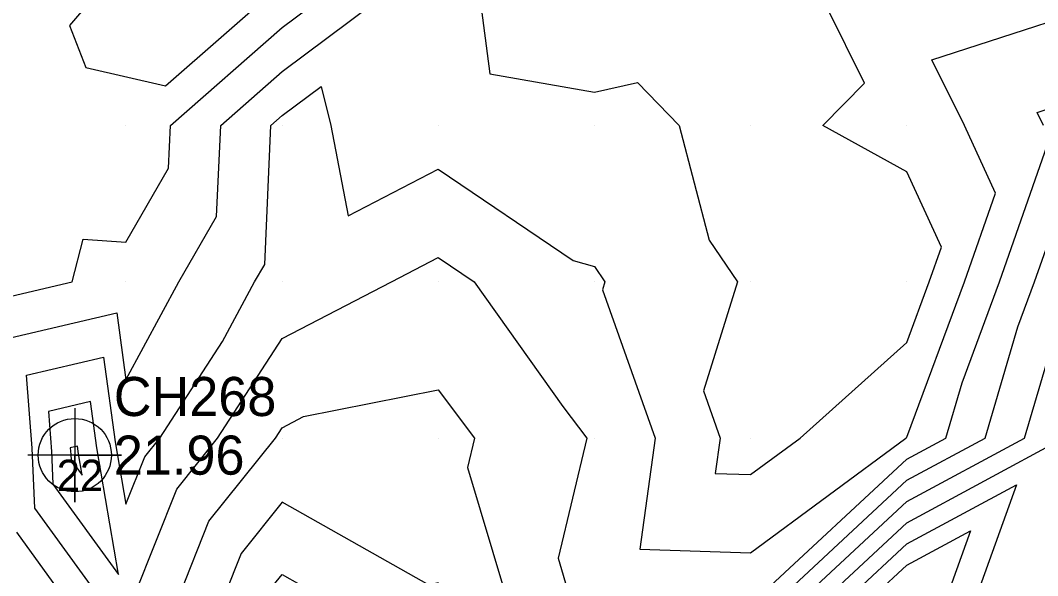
# Model space of a CAD drawing. Extents: x 2531902 to 2533249, y 715219 to 716099.
# Drawn here: x 2533033.2 to 2533098.4, y 715851.2 to 715886.7 of the extents above; entities that cross this region are included whole.
import ezdxf

# ---------------------------------------------------------------- set-up
doc = ezdxf.new("R2010")
doc.units = 0
for name, color, linetype in [('DTM Contours Major', 7, 'Continuous'), ('DTM Contours Major Text', 7, 'Continuous'), ('DTM Contours Minor', 7, 'Continuous'), ('Exist DTM QL2 LIDAR Elevation Point', 7, 'Continuous'), ('Exist DTM Regular Point CELL', 7, 'Continuous'), ('Exist DTM Regular Point Cogo Elevation', 7, 'Continuous'), ('Exist DTM Regular Point Cogo Number', 7, 'Continuous')]:
    doc.layers.add(name, color=color, linetype=linetype)

msp = doc.modelspace()

# ---------------------------------------------------------------- linework, layer by layer
at = {"layer": 'DTM Contours Major'}
for points in [[(2533058.684, 715946.051), (2533056.798, 715942.703), (2533049.015, 715914.041), (2533044.292, 715903.769), (2533045.261, 715900), (2533040, 715890.415), (2533039.46, 715890), (2533036.398, 715886.398), (2533037.436, 715883.718), (2533042.532, 715882.532), (2533050, 715889.091), (2533051.217, 715890), (2533054.899, 715895.101), (2533063.734, 715893.085)], [(2533075.512, 715846.541), (2533077.856, 715846.504), (2533079.467, 715848.554), (2533079.786, 715848.666), (2533082.141, 715850), (2533090, 715857.3), (2533095.009, 715860), (2533097.108, 715867.108), (2533098.179, 715870), (2533100, 715875.186), (2533111.816, 715879.234), (2533118.548, 715880.563)], [(2533041.774, 715810.454), (2533042.404, 715811.1), (2533043.161, 715818.289), (2533049.48, 715820), (2533040, 715827.811), (2533038.4, 715830), (2533038.956, 715831.044), (2533037.941, 715840), (2533038.308, 715841.692), (2533040, 715844.87), (2533043.452, 715850), (2533045.318, 715854.682), (2533049.57, 715860), (2533050, 715860.663), (2533051.38, 715861.38), (2533060, 715863.087), (2533062.327, 715860), (2533061.88, 715858.12), (2533064.295, 715850), (2533065.802, 715844.886), (2533070.3, 715846.623), (2533071.512, 715846.604)], [(2533037.204, 715857.62), (2533036.969, 715858.991), (2533036.901, 715859.49), (2533036.444, 715859.383), (2533036.478, 715858.952), (2533036.494, 715858.599), (2533037.204, 715857.62)]]:
    msp.add_lwpolyline(points, dxfattribs=at)
at = {"layer": 'DTM Contours Minor'}
for points in [[(2533030.819, 715868.651), (2533036.572, 715870), (2533037.27, 715872.73), (2533040, 715872.543), (2533042.738, 715877.262), (2533042.86, 715880), (2533050, 715886.271), (2533054.991, 715890)], [(2533032.225, 715866.334), (2533039.416, 715868.02), (2533040, 715863.727), (2533043.383, 715870), (2533045.813, 715874.187), (2533046.07, 715880), (2533050, 715883.451), (2533058.765, 715890)], [(2533062.426, 715890), (2533063.309, 715883.309), (2533070, 715882.124), (2533072.753, 715882.753), (2533075.419, 715880), (2533077.334, 715872.666), (2533079.15, 715870), (2533076.976, 715863.024), (2533078.051, 715860), (2533077.738, 715857.738), (2533080, 715857.664), (2533083.167, 715860), (2533090, 715866.124), (2533091.435, 715870), (2533092.212, 715872.212), (2533090, 715877.025), (2533084.628, 715880), (2533087.284, 715882.716), (2533084.877, 715887.562)], [(2533038.183, 715850), (2533034.175, 715855.527), (2533034.001, 715859.353), (2533033.632, 715864.017), (2533038.578, 715865.177), (2533039.313, 715859.771), (2533040, 715855.768), (2533041.206, 715858.794), (2533042.17, 715860), (2533046.183, 715866.183), (2533048.241, 715870), (2533048.887, 715871.113), (2533049.281, 715880), (2533050, 715880.631), (2533052.497, 715882.497), (2533053.116, 715880), (2533054.226, 715874.226), (2533060, 715877.202), (2533068.634, 715871.366), (2533070, 715870.975), (2533070.664, 715870), (2533070.506, 715869.494), (2533073.88, 715860), (2533072.899, 715852.899), (2533080, 715852.667), (2533089.943, 715860), (2533090, 715860.051), (2533093.683, 715870), (2533095.676, 715875.676), (2533093.69, 715880), (2533091.604, 715884.198), (2533105.712, 715888.793)], [(2533098.746, 715880), (2533098.332, 715880.834), (2533101.135, 715881.747)], [(2533080.681, 715850), (2533090, 715858.655), (2533092.494, 715860), (2533093.539, 715863.539), (2533095.931, 715870), (2533099.141, 715879.141)], [(2533040.577, 715850), (2533043.262, 715856.738), (2533045.87, 715860), (2533050, 715866.363), (2533057, 715870), (2533060, 715871.547), (2533062.288, 715870), (2533067.973, 715862.027), (2533069.501, 715860), (2533067.676, 715852.324), (2533068.367, 715850)], [(2533029.47, 715797.174), (2533034.584, 715802), (2533044.323, 715811.978), (2533044.889, 715817.354), (2533050.003, 715818.738), (2533059.408, 715829.085), (2533060.57, 715830.291), (2533063.024, 715841.321), (2533070.513, 715844.213), (2533076.394, 715844.12), (2533079.104, 715847.569), (2533079.64, 715847.757), (2533083.601, 715850), (2533090, 715855.944), (2533097.525, 715860), (2533100, 715868.383)], [(2533039.533, 715851.274), (2533038.141, 715859.381), (2533037.739, 715862.333), (2533035.038, 715861.7), (2533035.24, 715859.152), (2533035.334, 715857.063), (2533039.533, 715851.274)], [(2533032.179, 715798.448), (2533046.243, 715812.856), (2533046.618, 715816.418), (2533050.007, 715817.335), (2533056.239, 715824.192), (2533063.618, 715831.849), (2533065.373, 715839.735), (2533070.727, 715841.802), (2533074.931, 715841.736), (2533078.74, 715846.583), (2533079.494, 715846.847), (2533085.061, 715850), (2533090, 715854.588), (2533099.953, 715859.953)], [(2533029.774, 715794.896), (2533048.162, 715813.734), (2533048.347, 715815.482), (2533050.01, 715815.933), (2533053.069, 715819.299), (2533066.666, 715833.407), (2533067.721, 715838.149), (2533070.941, 715839.392), (2533073.469, 715839.352), (2533078.377, 715845.597), (2533079.348, 715845.938), (2533086.52, 715850), (2533090, 715853.232), (2533097.012, 715857.012), (2533093.228, 715846.455)], [(2533050, 715855.91), (2533047.374, 715852.626), (2533046.328, 715850), (2533040, 715840.598), (2533039.792, 715840.208), (2533039.747, 715840), (2533040, 715837.77), (2533043.949, 715836.051), (2533050, 715831.445), (2533054.295, 715840), (2533060, 715849.686), (2533061.673, 715845.079), (2533060.222, 715850), (2533060, 715850.748), (2533059.418, 715850.582), (2533050, 715855.91)], [(2533028.859, 715793.308), (2533049.964, 715814.518), (2533050.02, 715814.573), (2533051.407, 715815.969), (2533069.714, 715834.964), (2533070.069, 715836.563), (2533071.155, 715836.982), (2533072.007, 715836.969), (2533078.013, 715844.611), (2533079.202, 715845.028), (2533087.98, 715850), (2533090, 715851.876), (2533094.07, 715854.07), (2533090, 715842.716), (2533089.567, 715839.714), (2533089.539, 715839.548), (2533081.76, 715828.214), (2533064.829, 715810.719), (2533060.921, 715806.824), (2533041.394, 715786.547), (2533040.207, 715785.363), (2533038.711, 715783.801), (2533038.669, 715783.758), (2533033.901, 715779.797)], [(2533032.523, 715840), (2533033.857, 715846.143), (2533035.909, 715850), (2533033.015, 715853.991)], [(2533047.563, 715847.563), (2533049.203, 715850), (2533049.43, 715850.57), (2533050, 715851.282), (2533052.267, 715850), (2533052.22, 715842.22), (2533050.913, 715840), (2533050, 715838.182), (2533047.612, 715840), (2533047.563, 715847.563)]]:
    msp.add_lwpolyline(points, dxfattribs=at)
at = {"layer": 'Exist DTM QL2 LIDAR Elevation Point'}
for p, q in [((2533040, 715880), (2533040, 715880)), ((2533050, 715880), (2533050, 715880)), ((2533060, 715880), (2533060, 715880)), ((2533070, 715880), (2533070, 715880)), ((2533080, 715880), (2533080, 715880)), ((2533090, 715880), (2533090, 715880)), ((2533040, 715870), (2533040, 715870)), ((2533050, 715870), (2533050, 715870)), ((2533060, 715870), (2533060, 715870)), ((2533070, 715870), (2533070, 715870)), ((2533080, 715870), (2533080, 715870)), ((2533090, 715870), (2533090, 715870)), ((2533040, 715860), (2533040, 715860)), ((2533050, 715860), (2533050, 715860)), ((2533060, 715860), (2533060, 715860)), ((2533070, 715860), (2533070, 715860)), ((2533080, 715860), (2533080, 715860)), ((2533090, 715860), (2533090, 715860))]:
    msp.add_line(p, q, dxfattribs=at)
at = {"layer": 'Exist DTM Regular Point CELL'}
msp.add_lwpolyline([(2533036.73, 715861.911), (2533036.73, 715855.911), (2533036.73, 715858.911), (2533039.73, 715858.911), (2533033.73, 715858.911)], dxfattribs=at)
msp.add_circle((2533036.73, 715858.911), 2.344, dxfattribs=at)

# ---------------------------------------------------------------- texts
at = {"layer": 'DTM Contours Major Text'}
msp.add_text('22', height=2, dxfattribs=at).set_placement((2533035.574, 715856.62))
at = {"layer": 'Exist DTM Regular Point Cogo Elevation'}
msp.add_text('21.96', height=2.5, dxfattribs=at).set_placement((2533039.23, 715857.661))
at = {"layer": 'Exist DTM Regular Point Cogo Number'}
msp.add_text('CH268', height=2.5, dxfattribs=at).set_placement((2533039.23, 715861.411))

doc.saveas('drawing.dxf')
